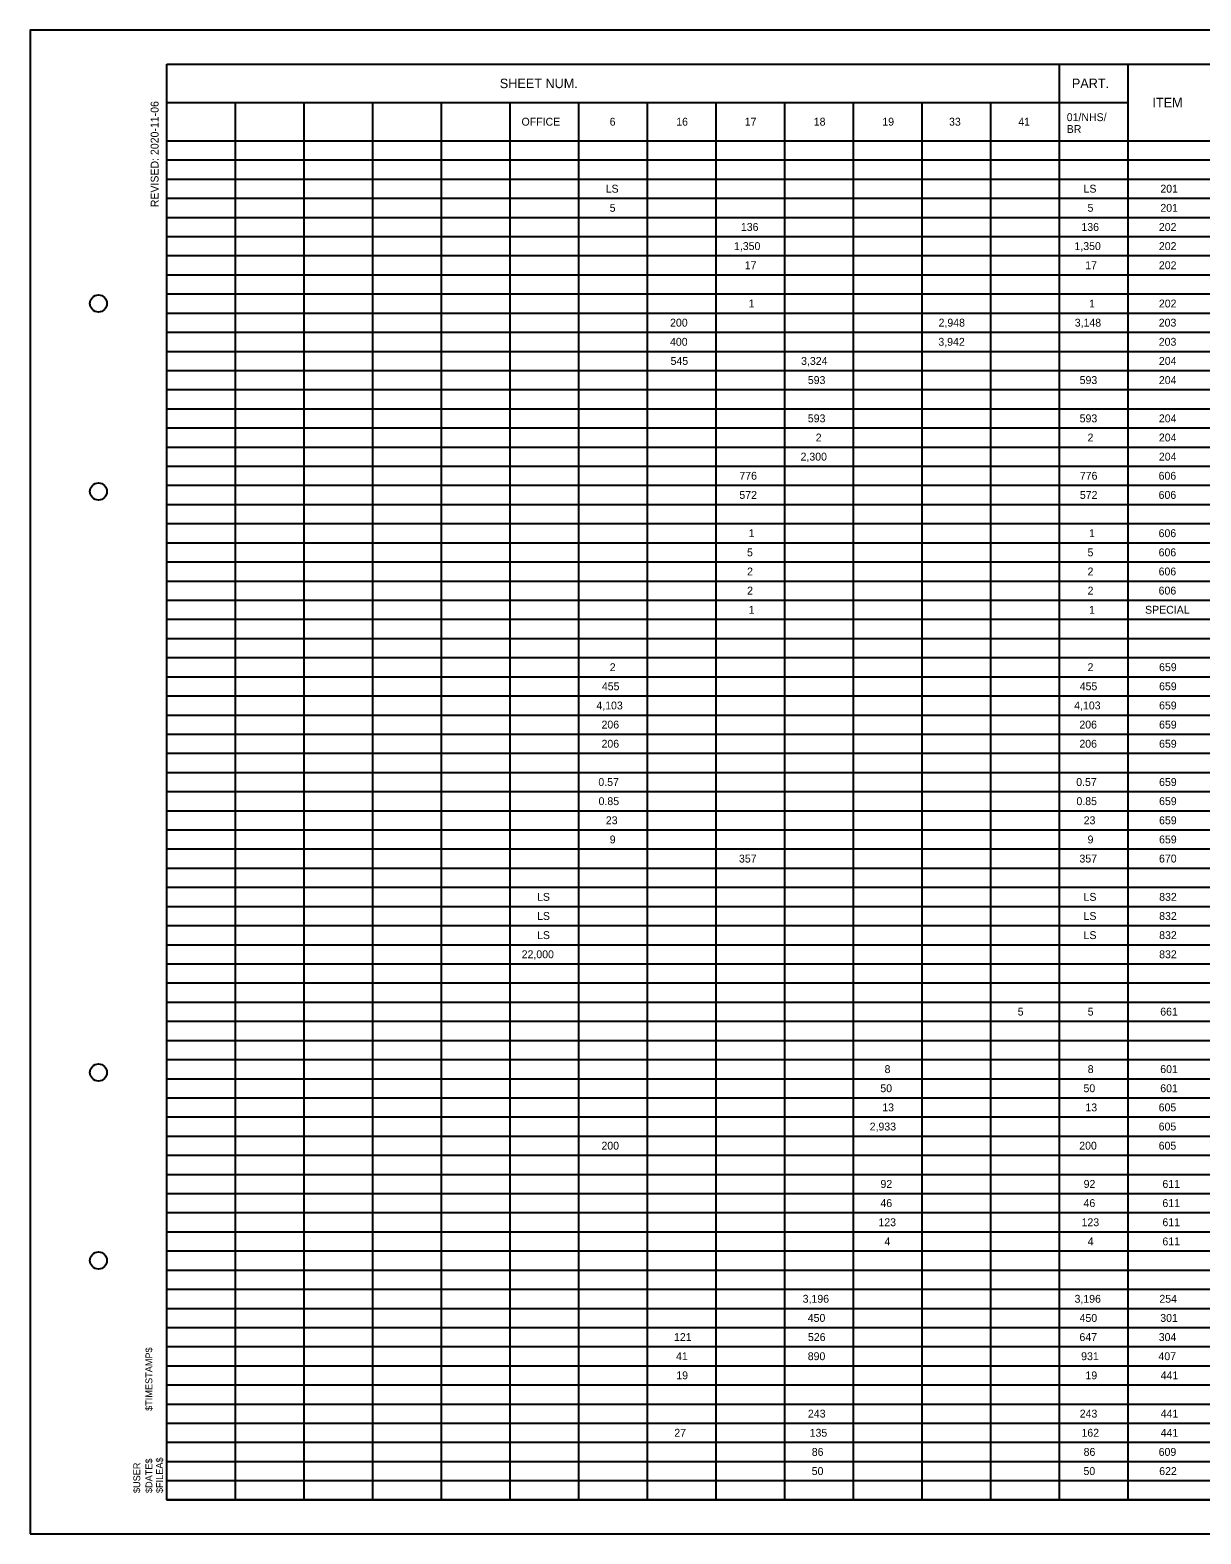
# Model space of a CAD drawing. Extents: x 0 to 34, y 0 to 22.
# Drawn here: x 0 to 17.13, y 0 to 22 of the extents above; entities that cross this region are included whole.
import ezdxf

# ---------------------------------------------------------------- set-up
doc = ezdxf.new("R2010")
doc.units = 0
for name, color, linetype in [('SH_Border', 7, 'Continuous'), ('SH_Cut_Line', 7, 'Continuous'), ('SH_Data', 7, 'Continuous'), ('SH_Text', 7, 'Continuous')]:
    doc.layers.add(name, color=color, linetype=linetype)

msp = doc.modelspace()

# ---------------------------------------------------------------- linework, layer by layer
at = {"layer": 'SH_Border'}
msp.add_lwpolyline([(2, 21.5), (33.5, 21.5), (33.5, 0.5), (2, 0.5)], close=True, dxfattribs=at)
for centre in [(1, 18), (1, 15.25), (1, 6.75), (1, 4)]:
    msp.add_circle(centre, 0.125, dxfattribs=at)
at = {"layer": 'SH_Cut_Line'}
msp.add_lwpolyline([(0, 0), (34, 0), (34, 22), (0, 22)], close=True, dxfattribs=at)
at = {"layer": 'SH_Text'}
for p, q in [((2, 21.5), (2, 21.5)), ((2, 21.5), (32.5, 21.5)), ((2, 0.5), (2, 21.5)), ((15.06, 0.5), (15.06, 21.5)), ((16.064, 0.5), (16.064, 21.5)), ((2, 20.94), (16.064, 20.94)), ((3.005, 0.5), (3.005, 20.94)), ((4.009, 0.5), (4.009, 20.94)), ((5.014, 0.5), (5.014, 20.94)), ((6.018, 0.5), (6.018, 20.94)), ((7.023, 0.5), (7.023, 20.94)), ((8.028, 0.5), (8.028, 20.94)), ((9.032, 0.5), (9.032, 20.94)), ((10.037, 0.5), (10.037, 20.94)), ((11.041, 0.5), (11.041, 20.94)), ((12.046, 0.5), (12.046, 20.94)), ((13.05, 0.5), (13.05, 20.94)), ((14.055, 0.5), (14.055, 20.94)), ((2, 20.38), (15.06, 20.38)), ((14.055, 20.38), (32.5, 20.38)), ((2, 20.1), (32.5, 20.1)), ((2, 19.82), (32.5, 19.82)), ((2, 19.54), (32.5, 19.54)), ((2, 19.26), (32.5, 19.26)), ((2, 18.98), (32.5, 18.98)), ((2, 18.7), (32.5, 18.7)), ((2, 18.42), (32.5, 18.42)), ((2, 18.14), (32.5, 18.14)), ((2, 17.86), (32.5, 17.86)), ((2, 17.58), (32.5, 17.58)), ((2, 17.3), (32.5, 17.3)), ((2, 17.02), (32.5, 17.02)), ((2, 16.74), (32.5, 16.74)), ((2, 16.46), (32.5, 16.46)), ((2, 16.18), (32.5, 16.18)), ((2, 15.9), (32.5, 15.9)), ((2, 15.62), (32.5, 15.62)), ((2, 15.34), (32.5, 15.34)), ((2, 15.06), (32.5, 15.06)), ((2, 14.78), (32.5, 14.78)), ((2, 14.5), (32.5, 14.5)), ((2, 14.22), (32.5, 14.22)), ((2, 13.94), (32.5, 13.94)), ((2, 13.66), (32.5, 13.66)), ((2, 13.38), (32.5, 13.38)), ((2, 13.1), (32.5, 13.1)), ((2, 12.82), (32.5, 12.82)), ((2, 12.54), (32.5, 12.54)), ((2, 12.26), (32.5, 12.26)), ((2, 11.98), (32.5, 11.98)), ((2, 11.7), (32.5, 11.7)), ((2, 11.42), (32.5, 11.42)), ((2, 11.14), (32.5, 11.14)), ((2, 10.86), (32.5, 10.86)), ((2, 10.58), (32.5, 10.58)), ((2, 10.3), (32.5, 10.3)), ((2, 10.02), (32.5, 10.02)), ((2, 9.74), (32.5, 9.74)), ((2, 9.46), (32.5, 9.46)), ((2, 9.18), (32.5, 9.18)), ((2, 8.9), (32.5, 8.9)), ((2, 8.62), (32.5, 8.62)), ((2, 8.34), (32.5, 8.34)), ((2, 8.06), (32.5, 8.06)), ((2, 7.78), (32.5, 7.78)), ((2, 7.5), (32.5, 7.5)), ((2, 7.22), (32.5, 7.22)), ((2, 6.94), (32.5, 6.94)), ((2, 6.66), (32.5, 6.66)), ((2, 6.38), (32.5, 6.38)), ((2, 6.1), (32.5, 6.1)), ((2, 5.82), (32.5, 5.82)), ((2, 5.54), (32.5, 5.54)), ((2, 5.26), (32.5, 5.26)), ((2, 4.98), (32.5, 4.98)), ((2, 4.7), (32.5, 4.7)), ((2, 4.42), (32.5, 4.42)), ((2, 4.14), (32.5, 4.14)), ((2, 3.86), (32.5, 3.86)), ((2, 3.58), (32.5, 3.58)), ((2, 3.3), (32.5, 3.3)), ((2, 3.02), (32.5, 3.02)), ((2, 2.74), (32.5, 2.74)), ((2, 2.46), (32.5, 2.46)), ((2, 2.18), (32.5, 2.18)), ((2, 1.9), (32.5, 1.9)), ((2, 1.62), (32.5, 1.62)), ((2, 1.34), (32.5, 1.34)), ((2, 1.06), (32.5, 1.06)), ((2, 0.78), (32.5, 0.78)), ((2, 0.5), (32.5, 0.5))]:
    msp.add_line(p, q, dxfattribs=at)

# ---------------------------------------------------------------- texts
at = {"layer": 'SH_Data'}
for s, p in [('$TIMESTAMP$', (1.788, 1.8)), ('$DATE$', (1.788, 0.598)), ('$FILEA$', (1.944, 0.598)), ('$USER', (1.611, 0.598))]:
    msp.add_text(s, height=0.1, rotation=89.9931, dxfattribs=at).set_placement(p)
at = {"layer": 'SH_Text'}
for s, height, p in [('SHEET NUM.', 0.1384, (6.872, 21.151)), ('PART.', 0.1384, (15.241, 21.151)), ('ITEM', 0.1384, (16.419, 20.871)), ('OFFICE', 0.1153, (7.19, 20.602)), ('6', 0.115, (8.479, 20.602)), ('16', 0.1153, (9.453, 20.602)), ('17', 0.1153, (10.455, 20.602)), ('18', 0.1153, (11.465, 20.602)), ('19', 0.1153, (12.468, 20.602)), ('33', 0.1153, (13.444, 20.602)), ('41', 0.1153, (14.457, 20.602)), ('01/NHS/', 0.1153, (15.166, 20.668)), ('BR', 0.1153, (15.166, 20.495)), ('LS', 0.1153, (8.421, 19.622)), ('LS', 0.1153, (15.412, 19.622)), ('201', 0.1153, (16.536, 19.622)), ('5', 0.115, (8.48, 19.342)), ('5', 0.115, (15.47, 19.342)), ('201', 0.1153, (16.536, 19.342)), ('136', 0.1153, (10.399, 19.062)), ('136', 0.1153, (15.381, 19.062)), ('202', 0.1153, (16.514, 19.062)), ('1,350', 0.1153, (10.298, 18.782)), ('1,350', 0.1153, (15.279, 18.782)), ('202', 0.1153, (16.514, 18.782)), ('17', 0.1153, (10.455, 18.502)), ('17', 0.1153, (15.436, 18.502)), ('202', 0.1153, (16.514, 18.502)), ('1', 0.115, (10.512, 17.942)), ('1', 0.115, (15.493, 17.942)), ('202', 0.1153, (16.514, 17.942)), ('200', 0.1153, (9.363, 17.662)), ('2,948', 0.1153, (13.291, 17.662)), ('3,148', 0.1153, (15.283, 17.662)), ('203', 0.1153, (16.512, 17.662)), ('400', 0.1153, (9.362, 17.382)), ('3,942', 0.1153, (13.288, 17.382)), ('203', 0.1153, (16.512, 17.382)), ('545', 0.1153, (9.37, 17.102)), ('3,324', 0.1153, (11.28, 17.102)), ('204', 0.1153, (16.514, 17.102)), ('593', 0.1153, (11.378, 16.822)), ('593', 0.1153, (15.355, 16.822)), ('204', 0.1153, (16.514, 16.822)), ('593', 0.1153, (11.378, 16.262)), ('593', 0.1153, (15.355, 16.262)), ('204', 0.1153, (16.514, 16.262)), ('2', 0.115, (11.494, 15.982)), ('2', 0.115, (15.471, 15.982)), ('204', 0.1153, (16.514, 15.982)), ('2,300', 0.1153, (11.272, 15.702)), ('204', 0.1153, (16.514, 15.702)), ('776', 0.1153, (10.377, 15.422)), ('776', 0.1153, (15.358, 15.422)), ('606', 0.1153, (16.51, 15.422)), ('572', 0.1153, (10.377, 15.142)), ('572', 0.1153, (15.358, 15.142)), ('606', 0.1153, (16.51, 15.142)), ('1', 0.115, (10.512, 14.582)), ('1', 0.115, (15.493, 14.582)), ('606', 0.1153, (16.51, 14.582)), ('5', 0.115, (10.489, 14.302)), ('5', 0.115, (15.47, 14.302)), ('606', 0.1153, (16.51, 14.302)), ('2', 0.115, (10.49, 14.022)), ('2', 0.115, (15.471, 14.022)), ('606', 0.1153, (16.51, 14.022)), ('2', 0.115, (10.49, 13.742)), ('2', 0.115, (15.471, 13.742)), ('606', 0.1153, (16.51, 13.742)), ('1', 0.115, (10.512, 13.462)), ('1', 0.115, (15.493, 13.462)), ('SPECIAL', 0.1153, (16.312, 13.462)), ('2', 0.115, (8.481, 12.622)), ('2', 0.115, (15.471, 12.622)), ('659', 0.1153, (16.517, 12.622)), ('455', 0.1153, (8.365, 12.342)), ('455', 0.1153, (15.356, 12.342)), ('659', 0.1153, (16.517, 12.342)), ('4,103', 0.1153, (8.285, 12.062)), ('4,103', 0.1153, (15.275, 12.062)), ('659', 0.1153, (16.517, 12.062)), ('206', 0.1153, (8.36, 11.782)), ('206', 0.1153, (15.351, 11.782)), ('659', 0.1153, (16.517, 11.782)), ('206', 0.1153, (8.36, 11.502)), ('206', 0.1153, (15.351, 11.502)), ('659', 0.1153, (16.517, 11.502)), ('0.57', 0.1153, (8.314, 10.942)), ('0.57', 0.1153, (15.305, 10.942)), ('659', 0.1153, (16.517, 10.942)), ('0.85', 0.1153, (8.317, 10.662)), ('0.85', 0.1153, (15.308, 10.662)), ('659', 0.1153, (16.517, 10.662)), ('23', 0.1153, (8.423, 10.382)), ('23', 0.1153, (15.414, 10.382)), ('659', 0.1153, (16.517, 10.382)), ('9', 0.115, (8.48, 10.102)), ('9', 0.115, (15.471, 10.102)), ('659', 0.1153, (16.517, 10.102)), ('357', 0.1153, (10.371, 9.822)), ('357', 0.1153, (15.352, 9.822)), ('670', 0.1153, (16.516, 9.822)), ('LS', 0.1153, (7.417, 9.262)), ('LS', 0.1153, (15.412, 9.262)), ('832', 0.1153, (16.518, 9.262)), ('LS', 0.1153, (7.417, 8.982)), ('LS', 0.1153, (15.412, 8.982)), ('832', 0.1153, (16.518, 8.982)), ('LS', 0.1153, (7.417, 8.702)), ('LS', 0.1153, (15.412, 8.702)), ('832', 0.1153, (16.518, 8.702)), ('22,000', 0.1153, (7.192, 8.422)), ('832', 0.1153, (16.518, 8.422)), ('5', 0.115, (14.449, 7.583)), ('5', 0.115, (15.473, 7.583)), ('661', 0.1153, (16.534, 7.583)), ('8', 0.115, (12.501, 6.742)), ('8', 0.115, (15.473, 6.742)), ('601', 0.1153, (16.534, 6.742)), ('50', 0.1153, (12.439, 6.462)), ('50', 0.1153, (15.411, 6.462)), ('601', 0.1153, (16.534, 6.462)), ('13', 0.1153, (12.467, 6.182)), ('13', 0.1153, (15.439, 6.182)), ('605', 0.1153, (16.511, 6.182)), ('2,933', 0.1153, (12.283, 5.902)), ('605', 0.1153, (16.511, 5.902)), ('200', 0.1153, (8.359, 5.622)), ('200', 0.1153, (15.349, 5.622)), ('605', 0.1153, (16.511, 5.622)), ('92', 0.1153, (12.441, 5.062)), ('92', 0.1153, (15.413, 5.062)), ('611', 0.1153, (16.566, 5.062)), ('46', 0.1153, (12.44, 4.782)), ('46', 0.1153, (15.412, 4.782)), ('611', 0.1153, (16.566, 4.782)), ('123', 0.1153, (12.411, 4.502)), ('123', 0.1153, (15.383, 4.502)), ('611', 0.1153, (16.566, 4.502)), ('4', 0.115, (12.5, 4.222)), ('4', 0.115, (15.472, 4.222)), ('611', 0.1153, (16.566, 4.222)), ('3,196', 0.1153, (11.303, 3.382)), ('3,196', 0.1153, (15.28, 3.382)), ('254', 0.1153, (16.521, 3.382)), ('450', 0.1153, (11.377, 3.102)), ('450', 0.1153, (15.354, 3.102)), ('301', 0.1153, (16.534, 3.102)), ('121', 0.1153, (9.42, 2.822)), ('526', 0.1153, (11.38, 2.822)), ('647', 0.1153, (15.352, 2.822)), ('304', 0.1153, (16.512, 2.822)), ('41', 0.1153, (9.45, 2.542)), ('890', 0.1153, (11.377, 2.542)), ('931', 0.1153, (15.377, 2.542)), ('407', 0.1153, (16.508, 2.542)), ('19', 0.1153, (9.454, 2.262)), ('19', 0.1153, (15.44, 2.262)), ('441', 0.1153, (16.54, 2.262)), ('243', 0.1153, (11.38, 1.702)), ('243', 0.1153, (15.356, 1.702)), ('441', 0.1153, (16.54, 1.702)), ('27', 0.1153, (9.425, 1.422)), ('135', 0.1153, (11.405, 1.422)), ('162', 0.1153, (15.382, 1.422)), ('441', 0.1153, (16.54, 1.422)), ('86', 0.1153, (11.436, 1.142)), ('86', 0.1153, (15.413, 1.142)), ('609', 0.1153, (16.511, 1.142)), ('50', 0.1153, (11.435, 0.862)), ('50', 0.1153, (15.411, 0.862)), ('622', 0.1153, (16.519, 0.862))]:
    msp.add_text(s, height=height, dxfattribs=at).set_placement(p)
msp.add_text('REVISED: 2020-11-06', height=0.11534, rotation=90, dxfattribs=at).set_placement((1.88, 19.409))

doc.saveas('drawing.dxf')
